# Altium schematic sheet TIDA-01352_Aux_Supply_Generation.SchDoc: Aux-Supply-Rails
size 431 x 279 mm; Date: Not shown in title block; ApprovedBy: Not shown in title block; CheckedBy: Not shown in title block; Author: Not shown in title block; CompanyName: Not shown in title block; DrawnBy: Sanjay Pithadia; Engineer: Sanjay Pithadia; Organization: Not shown in title block; Address1: Not shown in title block; Address2: Not shown in title block; Address3: Not shown in title block; Address4: Not shown in title block; DocumentNumber: 1; Revision: Use project parameter SCH_Rev; SheetNumber: 4; SheetTotal: 9; PageSetup: Record=PageOptions¦CenterHorizontal=True¦CenterVertical=True¦PrintScale=1.00¦XCorrection=1.00¦YCorrection=1.00¦PrintKind=0¦BorderSize=5000000¦LeftOffset=0¦BottomOffset=0¦Orientation=2¦PaperLength=1000¦PaperWidth=1000¦Scale=100¦PaperSource=15¦PrintQuality=600¦MediaType=1¦DitherType=10¦PaperKind=Letter¦PrintScaleMode=1
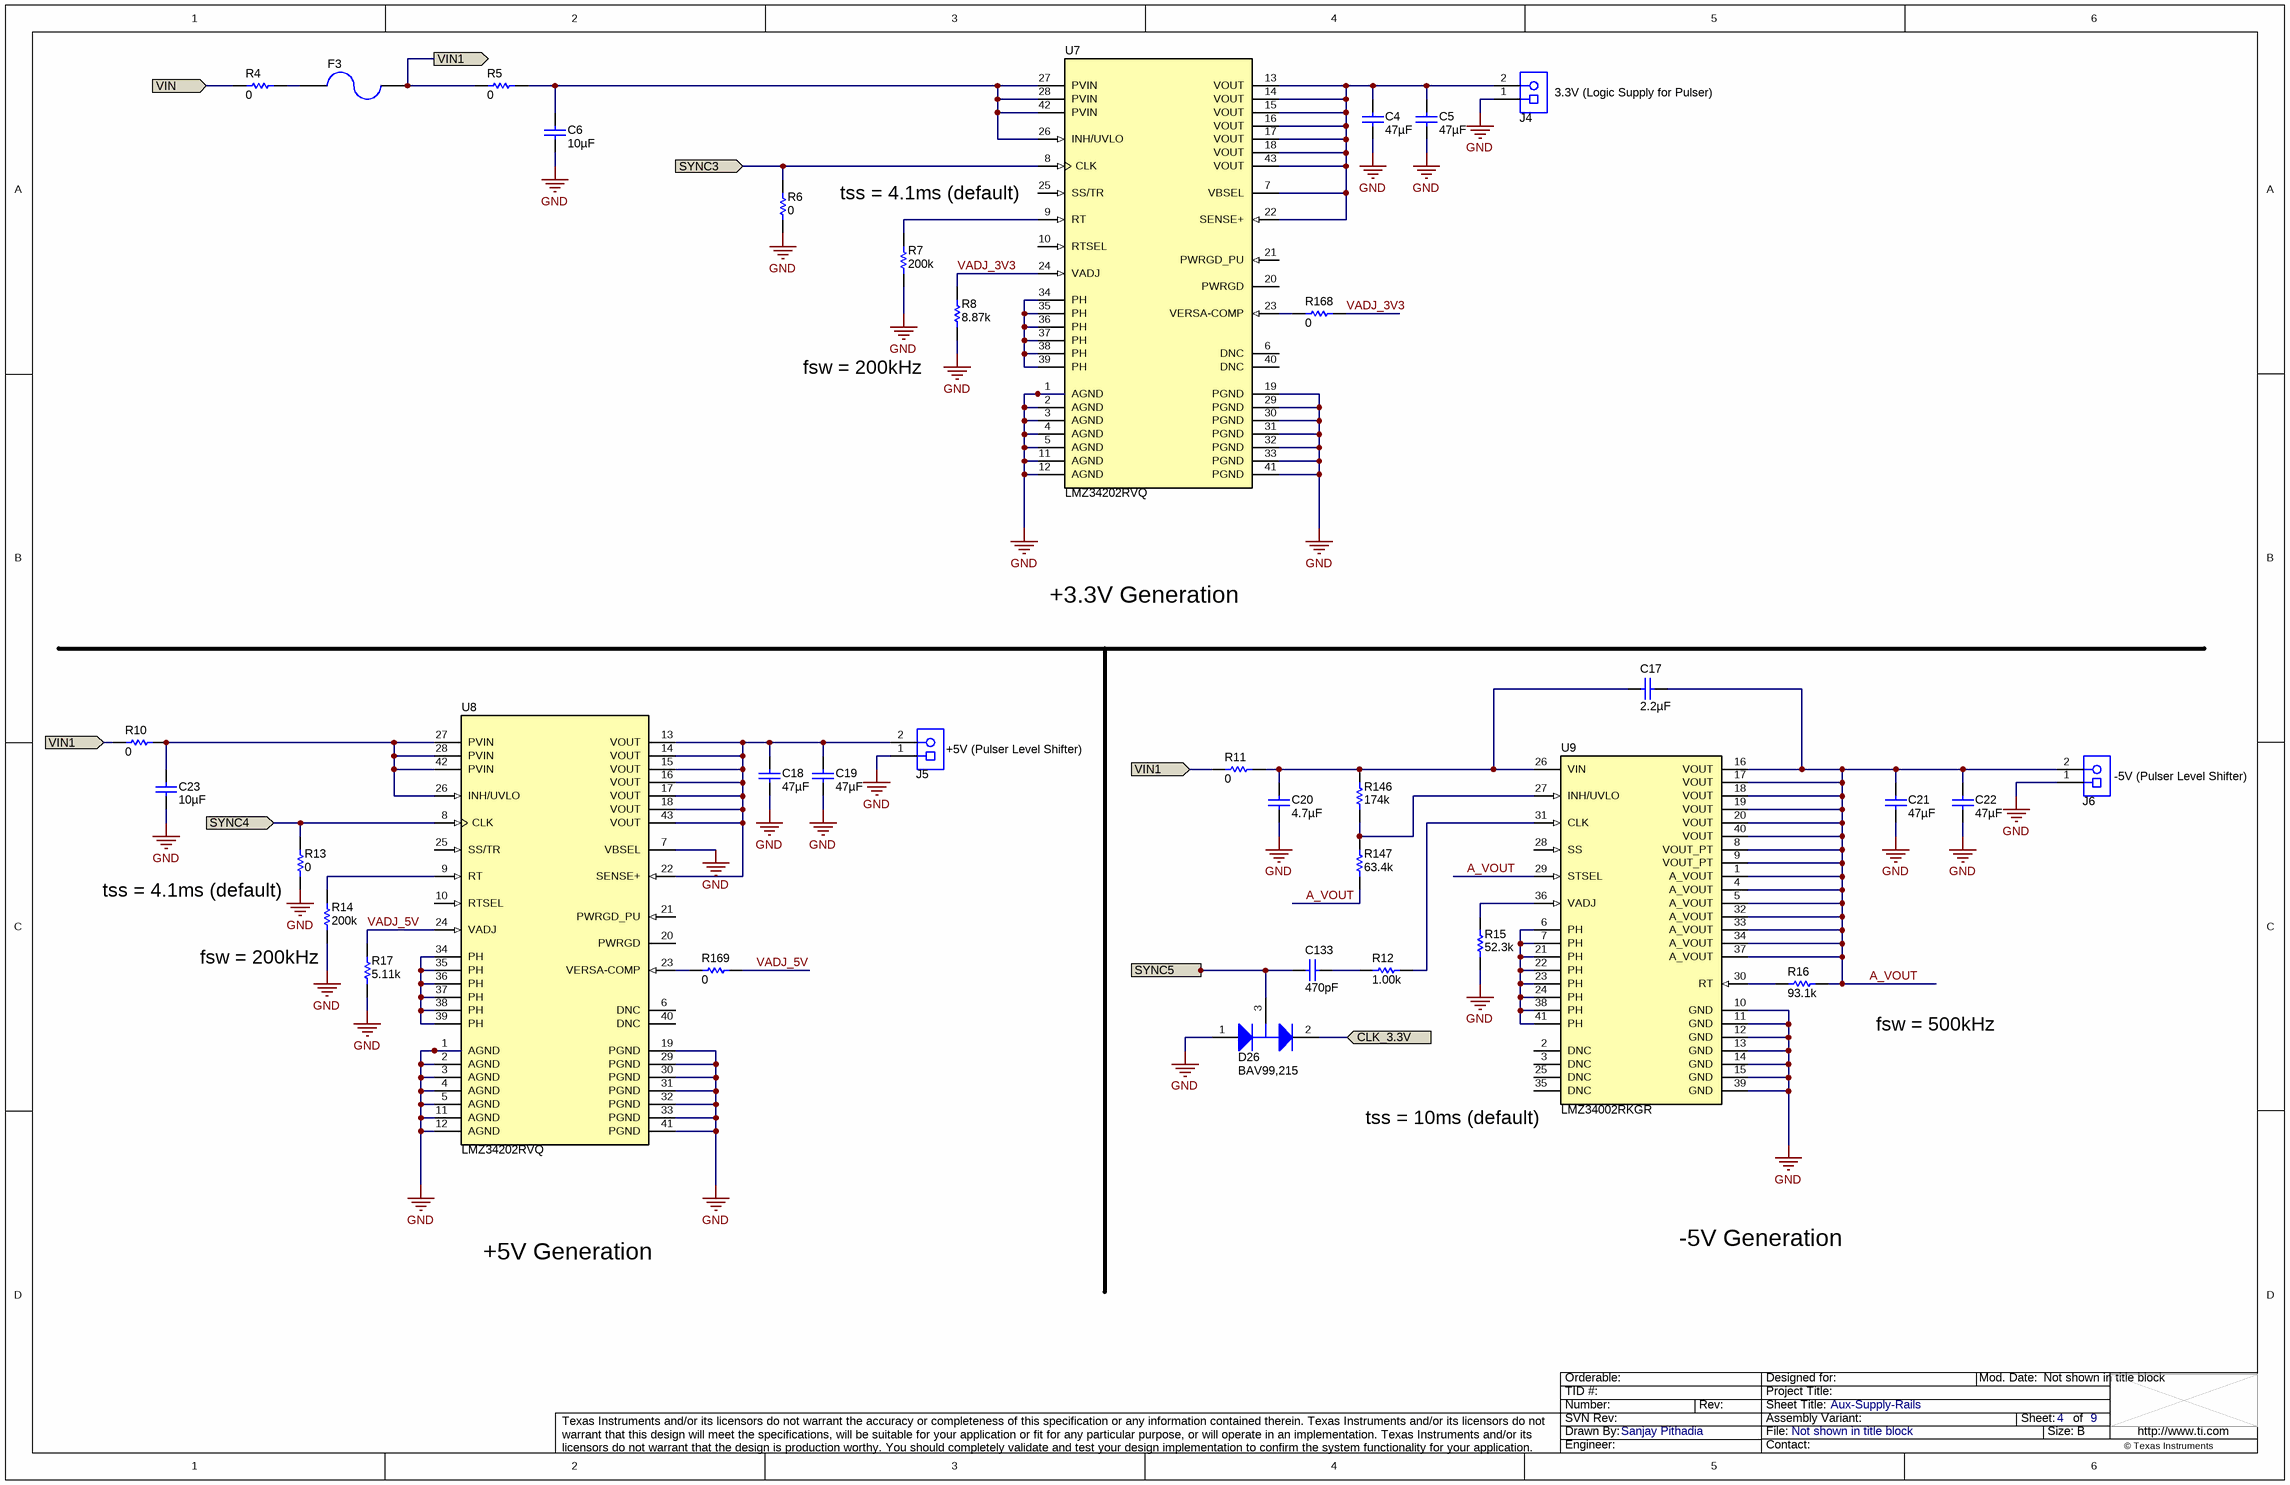
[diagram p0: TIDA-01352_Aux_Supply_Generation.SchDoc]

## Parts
C4  ValueDisplayed: 47µF  [1210_270]  (hidden comment: GRM32ER61C476KE15L)
C5  ValueDisplayed: 47µF  [1210_270]  (hidden comment: GRM32ER61C476KE15L)
C6  ValueDisplayed: 10µF  [1210_280]  (hidden comment: C3225X5R1H106K250AB)
C17  ValueDisplayed: 2.2µF  [0805_HV]  (hidden comment: C2012X5R1H225K125AB)
C18  ValueDisplayed: 47µF  [1210_270]  (hidden comment: GRM32ER61C476KE15L)
C19  ValueDisplayed: 47µF  [1210_270]  (hidden comment: GRM32ER61C476KE15L)
C20  ValueDisplayed: 4.7µF  [1206]  (hidden comment: C3216X5R1H475K085AB)
C21  ValueDisplayed: 47µF  [1210_270]  (hidden comment: GRM32ER61C476KE15L)
C22  ValueDisplayed: 47µF  [1210_270]  (hidden comment: GRM32ER61C476KE15L)
C23  ValueDisplayed: 10µF  [1210_280]  (hidden comment: C3225X5R1H106K250AB)
C133  ValueDisplayed: 470pF  [0603]  (hidden comment: 06035A471JAT2A)
D26  BAV99,215  [SOT-23]
F3  0679L9100-01  [Fuse_SSQ]  (value not drawn)
J4  282834-2  [TEC_282834-2]  (value not drawn)
J5  282834-2  [TEC_282834-2]  (value not drawn)
J6  282834-2  [TEC_282834-2]  (value not drawn)
R4  ValueDisplayed: 0  [5108]  (hidden comment: 5108)
R5  ValueDisplayed: 0  [0603]  (hidden comment: CRCW06030000Z0EA)
R6  ValueDisplayed: 0  [0603]  (hidden comment: CRCW06030000Z0EA)
R7  ValueDisplayed: 200k  [0603]  (hidden comment: CRCW0603200KFKEA)
R8  ValueDisplayed: 8.87k  [0603]  (hidden comment: CRCW06038K87FKEA)
R10  ValueDisplayed: 0  [0603]  (hidden comment: CRCW06030000Z0EA)
R11  ValueDisplayed: 0  [0603]  (hidden comment: CRCW06030000Z0EA)
R12  ValueDisplayed: 1.00k  [0603]  (hidden comment: CRCW06031K00FKEA)
R13  ValueDisplayed: 0  [0603]  (hidden comment: CRCW06030000Z0EA)
R14  ValueDisplayed: 200k  [0603]  (hidden comment: CRCW0603200KFKEA)
R15  ValueDisplayed: 52.3k  [0805_HV]  (hidden comment: CRCW080552K3FKEA)
R16  ValueDisplayed: 93.1k  [0805_HV]  (hidden comment: CRCW080593K1FKEA)
R17  ValueDisplayed: 5.11k  [0603]  (hidden comment: CRCW06035K11FKEA)
R146  ValueDisplayed: 174k  [0805_HV]  (hidden comment: CRCW0805174KFKEA)
R147  ValueDisplayed: 63.4k  [0805_HV]  (hidden comment: CRCW080563K4FKEA)
R168  ValueDisplayed: 0  [0603]  (hidden comment: CRCW06030000Z0EA)
R169  ValueDisplayed: 0  [0603]  (hidden comment: CRCW06030000Z0EA)
U7  LMZ34202RVQ  [RVQ0043A]
U8  LMZ34202RVQ  [RVQ0043A]
U9  LMZ34002RKGR  [RKG0041A]

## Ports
CLK_3.3V (in), SYNC3 (in), SYNC4 (in), SYNC5 (in), VIN1 (in), VIN1 (out), VIN (in)

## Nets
GND: C4.2 C5.2 C6.2 C18.2 C19.2 C20.2 C21.2 C22.2 C23.2 D26.1(A) J4.1 J5.1 J6.1 R6.1 R7.1 R8.1 R13.1 R14.1 R15.1 R17.1 U7.1(AGND) U7.2(AGND) U7.3(AGND) U7.4(AGND) U7.5(AGND) U7.11(AGND) U7.12(AGND) U7.19(PGND) U7.29(PGND) U7.30(PGND) U7.31(PGND) U7.32(PGND) U7.33(PGND) U7.41(PGND) U8.1(AGND) U8.2(AGND) U8.3(AGND) U8.4(AGND) U8.5(AGND) U8.7(VBSEL) U8.11(AGND) U8.12(AGND) U8.19(PGND) U8.29(PGND) U8.30(PGND) U8.31(PGND) U8.32(PGND) U8.33(PGND) U8.41(PGND) U9.10(GND) U9.11(GND) U9.12(GND) U9.13(GND) U9.14(GND) U9.15(GND) U9.39(GND)
A_VOUT: C17.1 C21.1 C22.1 J6.2 R16.2 R147.1 U9.1(A_VOUT) U9.4(A_VOUT) U9.5(A_VOUT) U9.8(VOUT_PT) U9.9(VOUT_PT) U9.16(VOUT) U9.17(VOUT) U9.18(VOUT) U9.19(VOUT) U9.20(VOUT) U9.29(STSEL) U9.32(A_VOUT) U9.33(A_VOUT) U9.34(A_VOUT) U9.37(A_VOUT) U9.40(VOUT)
CLK_3.3V: D26.2(K) ; port CLK_3.3V
SYNC3: R6.2 U7.8(CLK) ; port SYNC3
SYNC4: R13.2 U8.8(CLK) ; port SYNC4
SYNC5: C133.2 D26.3(C) ; port SYNC5
VADJ_3V3: R8.2 R168.1 U7.24(VADJ)
VADJ_5V: R17.2 R169.1 U8.24(VADJ)
VIN: R4.1 ; port VIN
VIN1: F3.1 R5.2 R10.2 R11.2 ; port VIN1
NetC4_1: C4.1 C5.1 J4.2 U7.7(VBSEL) U7.13(VOUT) U7.14(VOUT) U7.15(VOUT) U7.16(VOUT) U7.17(VOUT) U7.18(VOUT) U7.22(SENSE+) U7.43(VOUT)
NetC6_1: C6.1 R5.1 U7.26(INH/UVLO) U7.27(PVIN) U7.28(PVIN) U7.42(PVIN)
NetC17_2: C17.2 C20.1 R11.1 R146.2 U9.26(VIN)
NetC18_1: C18.1 C19.1 J5.2 U8.13(VOUT) U8.14(VOUT) U8.15(VOUT) U8.16(VOUT) U8.17(VOUT) U8.18(VOUT) U8.22(SENSE+) U8.43(VOUT)
NetC23_1: C23.1 R10.1 U8.26(INH/UVLO) U8.27(PVIN) U8.28(PVIN) U8.42(PVIN)
NetC133_1: C133.1 R12.2
NetF3_2: F3.2 R4.2
NetR7_2: R7.2 U7.9(RT)
NetR12_1: R12.1 U9.31(CLK)
NetR14_2: R14.2 U8.9(RT)
NetR15_2: R15.2 U9.36(VADJ)
NetR16_1: R16.1 U9.30(RT)
NetR146_1: R146.1 R147.2 U9.27(INH/UVLO)
NetR168_2: R168.2 U7.23(VERSA-COMP)
NetR169_2: R169.2 U8.23(VERSA-COMP)
NetU7_34: U7.34(PH) U7.35(PH) U7.36(PH) U7.37(PH) U7.38(PH) U7.39(PH)
NetU8_34: U8.34(PH) U8.35(PH) U8.36(PH) U8.37(PH) U8.38(PH) U8.39(PH)
NetU9_6: U9.6(PH) U9.7(PH) U9.21(PH) U9.22(PH) U9.23(PH) U9.24(PH) U9.38(PH) U9.41(PH)

Not connected (* = marked no-connect by the designer): U7 6(DNC) 10(RTSEL) 20(PWRGD) 21(PWRGD_PU) 25(SS/TR) 40(DNC); U8 6(DNC) 10(RTSEL) 20(PWRGD) 21(PWRGD_PU) 25(SS/TR) 40(DNC); U9 2(DNC) 3(DNC) 25(DNC) 28(SS) 35(DNC)

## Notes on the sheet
- (near J4) 3.3V (Logic Supply for Pulser)
- tss = 4.1ms (default)
- (near R8) fsw = 200kHz
- +3.3V Generation
- (near J5) +5V (Pulser Level Shifter)
- (near J6) -5V (Pulser Level Shifter)
- (near R13) tss = 4.1ms (default)
- (near R14) fsw = 200kHz
- fsw = 500kHz
- (near U9) tss = 10ms (default)
- -5V Generation
- +5V Generation

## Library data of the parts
C4 C5 C18 C19 C21 C22 = GRM32ER61C476KE15L: CAP, CERM, 47 µF, 16 V, +/- 10%, X5R, 1210; Manufacturer: MuRata; Polarized: N; CompType: Capacitor; Value: 47uF; U/M: EA; Cap_F: 0.000047; Tolerance_%: 10; Value1: Unknown; VDC_V: 16; Value2: 16V; TaMin_C: -55; TaMax_C: 85; Cap_Case: 1210; SizeArea_mm2: 8; SizeAreaWB_mm2: 14.7; SizeX_mm: 3.2; SizeY_mm: 2.5; SizeZ_mm: 2.7; AEC Category: Q200
C6 C23 = C3225X5R1H106K250AB: CAP, CERM, 10 µF, 50 V, +/- 10%, X5R, 1210; Manufacturer: TDK; Polarized: N; CompType: Capacitor; Value: 10uF; U/M: EA; Cap_F: 0.00001; Tolerance_%: 10; Value1: Unknown; VDC_V: 50; Value2: 50V; TaMin_C: -55; TaMax_C: 85; Cap_Case: 1210; SizeArea_mm2: 8; SizeAreaWB_mm2: 14.7; SizeX_mm: 3.2; SizeY_mm: 2.5; SizeZ_mm: 2.8; AEC Category: Q200
C17 = C2012X5R1H225K125AB: CAP, CERM, 2.2 µF, 50 V, +/- 10%, X5R, 0805; Manufacturer: TDK; Polarized: N; CompType: Capacitor; Value: 2.2uF; U/M: EA; Cap_F: 0.0000022; Tolerance_%: 10; ESR_ohm: 0.00366; Value1: 0.00366 ohm; VDC_V: 50; Value2: 50V; IRMS_A: 3.41207; TaMin_C: -55; TaMax_C: 85; Cap_Case: 0805; SizeArea_mm2: 2.5; SizeAreaWB_mm2: 6.75; SizeX_mm: 2; SizeY_mm: 1.25; SizeZ_mm: 1.45; AEC Category: Q200
C20 = C3216X5R1H475K085AB: CAP, CERM, 4.7 µF, 50 V, +/- 10%, X5R, 1206; Manufacturer: TDK; Polarized: N; CompType: Capacitor; Value: 4.7uF; U/M: EA; Cap_F: 0.0000047; Tolerance_%: 10; ESR_ohm: 0.003785; Value1: 0.003785 ohm; VDC_V: 50; Value2: 50V; IRMS_A: 3.73011; TaMin_C: -55; TaMax_C: 85; SizeArea_mm2: 5.12; SizeAreaWB_mm2: 10.92; SizeX_mm: 3.2; SizeY_mm: 1.6; SizeZ_mm: 1.35; AEC Category: Q200
C133 = 06035A471JAT2A: CAP, CERM, 470 pF, 50 V, +/- 5%, C0G/NP0, 0603; Manufacturer: AVX; Polarized: N; CompType: Capacitor; Value: 470pF; U/M: EA; Cap_F: 0.00000000047; Tolerance_%: 5; ESR_ohm: 0.063; Value1: 0.063 ohm; VDC_V: 50; Value2: 50V; TaMin_C: -55; TaMax_C: 125; SizeArea_mm2: 1.28; SizeAreaWB_mm2: 4.68; SizeX_mm: 1.6; SizeY_mm: 0.8; SizeZ_mm: 1; AEC Category: Q200
D26 = BAV99,215: Diode, Switching, 100 V, 0.215 A, SOT-23; Manufacturer: Nexperia; SymbolCreator: a0412235; U/M: EA; Vf_V: 1.25; Value: 100V; Value1: 0.215A; Value2: 1.25V; Io_A: 0.215; Vr_V: 100; TJmax_C: 150; SizeAreaWB_mm2: 14; SizeArea_mm2: 7.5; SizeX_mm: 2.5; SizeY_mm: 3; SizeZ_mm: 1.1; AEC Category: Q101
F3 = SSQ 8: FUSE BRD MNT 10A 125VAC/VDC; Manufacturer: Bel Fuse; VDC_V: 125; Interrupt_AC: 50; Irating_A: 8; Rtyp_Ohm: 0.008; MeltingTyp: 26
J4-J6 = 282834-2: Terminal Block, 2x1, 2.54mm, TH; Manufacturer: TE Connectivity; SymbolCreator: a0412235
R4 = 5108: RES, 0, 1%, 0.5 W, 1206; Manufacturer: Keystone; CompType: Resistor; Value: 0; Tolerance_%: 1; Power_W: 0.5; Value2: 0.5W; TempCo: ppm/C; SizeArea_mm2: 5.185; SizeX_mm: 3.05; SizeY_mm: 1.7; SizeZ_mm: 0.84; U/M: EA; AEC Category: Q200; AEC Qualified: N
R5 R6 R10 R11 R13 R168 R169 = CRCW06030000Z0EA: RES, 0, 5%, 0.1 W, 0603; Manufacturer: Vishay-Dale; CompType: Resistor; Value: 0; Value_Code: 0000; Tolerance_%: 5; Power_W: 0.1; Value2: 0.1W; VDC_V: 75; TempCo: 200 ppm/C; SizeArea_mm2: 1.28; SizeX_mm: 1.6; SizeY_mm: 0.8; SizeZ_mm: 1; EIA_Code: E24; U/M: EA; AEC Category: Q200
R7 R14 = CRCW0603200KFKEA: RES, 200 k, 1%, 0.1 W, 0603; Manufacturer: Vishay-Dale; CompType: Resistor; Value: 200k; Res_ohm: 200000; Tolerance_%: 1; Power_W: 0.1; Value2: 0.1W; VDC_V: 75; TempCo: 100 ppm/C; SizeArea_mm2: 1.28; SizeX_mm: 1.6; SizeY_mm: 0.8; EIA_Code: E96; U/M: EA; AEC Category: Q200
R8 = CRCW06038K87FKEA: RES, 8.87 k, 1%, 0.1 W, 0603; Manufacturer: Vishay-Dale; CompType: Resistor; Value: 8.87k; Res_ohm: 8870; Value_Code: 8k87; Tolerance_%: 1; Power_W: 0.1; Value2: 0.1W; VDC_V: 75; TempCo: 100 ppm/C; SizeArea_mm2: 1.28; SizeX_mm: 1.6; SizeY_mm: 0.8; EIA_Code: E96; U/M: EA; AEC Category: Q200
R12 = CRCW06031K00FKEA: RES, 1.00 k, 1%, 0.1 W, 0603; Manufacturer: Vishay-Dale; CompType: Resistor; Value: 1.00k; Res_ohm: 1000; Value_Code: 1k00; Tolerance_%: 1; Power_W: 0.1; Value2: 0.1W; VDC_V: 75; TempCo: 100 ppm/C; SizeArea_mm2: 1.28; SizeX_mm: 1.6; SizeY_mm: 0.8; EIA_Code: E96; U/M: EA; AEC Category: Q200
R15 = CRCW080552K3FKEA: RES, 52.3 k, 1%, 0.125 W, 0805; Manufacturer: Vishay-Dale; CompType: Resistor; Value: 52.3k; Res_ohm: 52300; Value_Code: 52k3; Tolerance_%: 1; Power_W: 0.125; Value2: 0.125W; VDC_V: 150; TempCo: 100 ppm/C; SizeArea_mm2: 2.5; SizeX_mm: 2; SizeY_mm: 1.25; SizeZ_mm: 1.45; EIA_Code: E96; U/M: EA; AEC Category: Q200
R16 = CRCW080593K1FKEA: RES, 93.1 k, 1%, 0.125 W, 0805; Manufacturer: Vishay-Dale; CompType: Resistor; Value: 93.1k; Res_ohm: 93100; Value_Code: 93k1; Tolerance_%: 1; Power_W: 0.125; Value2: 0.125W; VDC_V: 150; TempCo: 100 ppm/C; SizeArea_mm2: 2.5; SizeX_mm: 2; SizeY_mm: 1.25; SizeZ_mm: 1.45; EIA_Code: E96; U/M: EA; AEC Category: Q200
R17 = CRCW06035K11FKEA: RES, 5.11 k, 1%, 0.1 W, 0603; Manufacturer: Vishay-Dale; CompType: Resistor; Value: 5.11k; Res_ohm: 5110; Value_Code: 5k11; Tolerance_%: 1; Power_W: 0.1; Value2: 0.1W; VDC_V: 75; TempCo: 100 ppm/C; SizeArea_mm2: 1.28; SizeX_mm: 1.6; SizeY_mm: 0.8; EIA_Code: E96; U/M: EA; AEC Category: Q200
R146 = CRCW0805174KFKEA: RES, 174 k, 1%, 0.125 W, 0805; Manufacturer: Vishay-Dale; CompType: Resistor; Value: 174k; Res_ohm: 174000; Tolerance_%: 1; Power_W: 0.125; Value2: 0.125W; VDC_V: 150; TempCo: 100 ppm/C; SizeArea_mm2: 2.5; SizeX_mm: 2; SizeY_mm: 1.25; SizeZ_mm: 1.45; EIA_Code: E96; U/M: EA; AEC Category: Q200
R147 = CRCW080563K4FKEA: RES, 63.4 k, 1%, 0.125 W, 0805; Manufacturer: Vishay-Dale; CompType: Resistor; Value: 63.4k; Res_ohm: 63400; Value_Code: 63k4; Tolerance_%: 1; Power_W: 0.125; Value2: 0.125W; VDC_V: 150; TempCo: 100 ppm/C; SizeArea_mm2: 2.5; SizeX_mm: 2; SizeY_mm: 1.25; SizeZ_mm: 1.45; EIA_Code: E96; U/M: EA; AEC Category: Q200
U7 U8 = LMZ34202RVQ: SIMPLE SWITCHER 4.5-V to 42-V Input, 2-A Power Module, RVQ00043A (B3QFN-43); Manufacturer: Texas Instruments; SymbolCreator: Altium; SizeArea_mm2: 100; SizeAreaWB_mm2: 144; SizeX_mm: 10; SizeZ_mm: 4.4; CompType: IC; U/M: EA
U9 = LMZ34002RKGR: 4.5-V to 40-V Input, 15-W, Negative Output, Integrated Power Solution, RKG0041A (B1QFN-41); Alternate PartNumber: LMZ34002RKGT; Manufacturer: Texas Instruments; SymbolCreator: a0799628; SizeArea_mm2: 99; SizeAreaWB_mm2: 143; SizeX_mm: 9; SizeY_mm: 11; SizeZ_mm: 2.9; CompType: IC; U/M: EA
